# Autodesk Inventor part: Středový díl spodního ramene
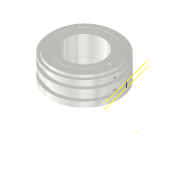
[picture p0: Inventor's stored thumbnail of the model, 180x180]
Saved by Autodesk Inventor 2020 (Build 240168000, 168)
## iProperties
Created: 2025-03
Part Number: Středový díl spodního ramene
Material: Ocel
Document SubType Name: Modeling
Designer: doma
Density: 7.85 g/cm^3
Appearance: Ocel
Mass: 3050.87 g
Surface Area: 596.38 cm^2
Volume: 388.646 cm^3
Author: doma
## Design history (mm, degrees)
sketch "Náčrt1"
  geometry: L1 (84.699, 80.344)-(55.699, 80.344); L2 (55.699, 80.344)-(55.699, 90.344); L3 (55.699, 90.344)-(62.199, 90.344); L4 (62.199, 90.344)-(62.199, 100.344); L5 (62.199, 100.344)-(55.699, 100.344); L6 (55.699, 100.344)-(55.699, 110.344); L7 (55.699, 110.344)-(62.199, 110.344); L8 (62.199, 110.344)-(62.199, 120.344); L9 (62.199, 120.344)-(55.699, 120.344); L10 (55.699, 120.344)-(55.699, 125.344); L11 (55.699, 125.344)-(84.699, 125.344); L12 (84.699, 125.344)-(84.699, 80.344); L13 (119.699, 125.344)-(119.699, 80.344); 1 further point
  constraints: 26 end point, 8 perpendicular, 6 point on line, 1 horizontal, 1 vertical
  dimensions: "d0" = 10 distance of L1.end L2.end; "d1" = 10 distance of L3.end L4.end; "d2" = 10 distance of L5.end L6.end; "d3" = 10 distance of L7.end L8.end; "d4" = 5 distance of L9.end L10.end; "d7" = 57.5 distance between parallel lines of L13 L4; "d8" = 35 distance between parallel lines of L13 L12; "d9" = 64 distance between parallel lines of L13 L2
revolve "Rotace1" sketch "Náčrt1" stored, may be unused: angle "d10" = 90 deg
sketch "Náčrt3"
  geometry: C1 r 35 at (0, 0); C2 r 59 at (0, 0); 1 further point
  constraints: 2 centre point, 1 coincident
  dimensions: "d16" = 118 diameter of C2
extrude "Vysunutí2" join sketch "Náčrt3" distance "d17" = 5; taper "d18" = 0 deg
sketch "Náčrt4"
  geometry: C1 r 50 at (0, 0); C2 r 45 at (0, 0); 1 further point
  constraints: 2 centre point, 1 coincident
  dimensions: "d19" = 100 diameter of C1; "d20" = 90 diameter of C2
extrude "Vysunutí3" cut sketch "Náčrt4" distance "d21" = 0.5; taper "d22" = 0 deg
revolve "Rotace2" stored, may be unused: angle "d28" = 90 deg
node "Pracovní rovina1"
sketch "Náčrt6"
  geometry: L1 (-7.5, 35)-(-7.5, -35) reference; L2 (-12.5, -35)-(-12.5, 35) reference; L3 (-5, -64)-(-5, 64) reference; L4 (-5, 0)-(-15, 0); L5 (-15, -57.5)-(-15, 57.5) reference; L6 (15, -57.5)-(15, 57.5) reference; L7 (15, 0)-(5, 0); L8 (5, -57.5)-(5, 57.5) reference; 3 further points
  constraints: 6 midpoint, 4 end point
sketch "Náčrt7"
  geometry: L1 (45, 0)-(50, 0); C1 r 50 at (0, 0) reference; C2 r 45 at (0, 0) reference; C3 r 2 at (47.5, 0); 4 further points
  constraints: 2 end point, 2 horizontal alignment, 1 centre point, 1 coincident, 1 horizontal, 1 midpoint, 2 other
  dimensions: "d30" = 4 diameter of C3
hole "Díra1" sketch "Náčrt7" at (47.5, 0) diameter "d31" = 4; stored, may be unused: countersink angle "d35" = 90 deg, drill point angle "d37" = 118 deg; dims "d32" = 12, "d33" = 4, "d34" = 2, "d36" = 15
hole "Díra2" sketch "Náčrt6" diameter "d38" = 6.917; stored, may be unused: countersink angle "d42" = 90 deg, drill point angle "d44" = 118 deg; dims "d39" = 15, "d40" = 4, "d41" = 2, "d43" = 20
node "Pracovní rovina3"
  node "Pracovní rovina2"
sketch "Náčrt8"
  geometry: L1 (-22.5, -57.5)-(-22.5, 57.5) reference; L2 (-22.5, 0)-(-32.5, 0); L3 (-32.5, -57.5)-(-32.5, 57.5) reference; 2 further points
  constraints: 3 midpoint, 2 end point
hole "Díra3" sketch "Náčrt8" diameter "d46" = 6.917; stored, may be unused: countersink angle "d50" = 90 deg, drill point angle "d52" = 118 deg; dims "d47" = 15, "d48" = 4, "d49" = 2, "d51" = 20
sketch "Náčrt9"
  geometry: C1 r 45 at (0, 0) reference; C2 r 50 at (0, 0) reference; 1 further point
extrude "Vysunutí4" cut sketch "Náčrt9" distance "d53" = 0.5; taper "d54" = 0 deg
sketch "Náčrt10"
  geometry: C1 r 2 at (47.5, 0) reference; 1 further point
extrude "Vysunutí5" cut sketch "Náčrt10" distance "d55" = 15; taper "d56" = 0 deg
hole "Díra4" sketch "Náčrt8" diameter "d57" = 4; stored, may be unused: countersink angle "d61" = 90 deg, drill point angle "d63" = 118 deg; dims "d58" = 6, "d59" = 4, "d60" = 2, "d62" = 8
node "Těleso1"
sketch "Náčrt5"
  geometry: L1 (119.699, 80.344)-(119.699, 105.344); L2 (84.199, 95.344)-(84.199, 97.844); L3 (84.199, 97.844)-(84.699, 97.844); L4 (84.199, 95.344)-(84.199, 92.844); L5 (84.199, 92.844)-(84.699, 92.844); L6 (84.699, 97.844)-(84.699, 92.844); 1 further point
  constraints: 12 end point, 2 vertical
  dimensions: "d24" = 25 distance of L1.start L1.end; "d26" = 2.5 distance of L2.start L2.end; "d27" = 2.5 distance of L2.start L4.end
node "Promítnutá smyčka1"
node "Pracovní osa1"
other parameters: "d45" = 15 deg
